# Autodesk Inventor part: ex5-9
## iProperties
Shininess: 64.0
Length Units: 11272
Angle Units: 11279
Time Units: 11290
Mass Units: 11286
Length Display Precision: 3
Angle Display Precision: 2
Compacted: True
Part Number: ex5-9
Document SubType Name: Modeling
Created: 2003-11
Designer: Elise Moss
Cost Center: 0.1 lbmass
Authority: 1.93 in^3
Manufacturer: Standard
Standards Organization: Custom
Density: 0.0
Volumn: 0.0
Area: 0.0
PropertySet Name: Model Information
Control State: 0
Master: False
Checked Out: False
SaveDate: 2003-11-14
SaveTime: 18:51
TotalMass: 0.1 lbmass
TotalVolume: 1.93 in^3
Author: Elise Moss
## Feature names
1. Loft1
2. Shell1
3. Extrusion1
4. Sweep1
5. Extrusion2
6. Coil1
